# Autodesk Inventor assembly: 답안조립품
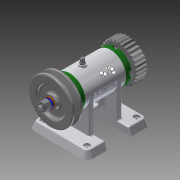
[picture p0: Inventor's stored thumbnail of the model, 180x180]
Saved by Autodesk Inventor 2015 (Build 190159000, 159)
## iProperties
Created: 2016-07
Part Number: 답안조립품
Document SubType Name: Assembly
Designer: LineLG02
Author: LineLG02
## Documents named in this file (16)
- C:\Users\LineLG02\Desktop\답안조립품.iam
- C:\Users\LineLG02\Desktop\본체.ipt
- C:\Users\LineLG02\Desktop\베어링 15 x 32 x 9.ipt
- C:\Users\LineLG02\Desktop\커버.ipt
- C:\Users\LineLG02\Desktop\볼트 M4 x 12.ipt
- C:\Users\LineLG02\Desktop\오일 실 15 25 7.ipt
- C:\Users\LineLG02\Desktop\축.ipt
- C:\Users\LineLG02\Desktop\키 3 x 3 x 12.ipt
- C:\Users\LineLG02\Desktop\V벨트풀리.ipt
- C:\Users\LineLG02\Desktop\스퍼기어.ipt
- C:\Users\LineLG02\Desktop\와셔 8x17.ipt
- C:\Users\LineLG02\Desktop\스프링와셔 8.ipt
- C:\Users\LineLG02\Desktop\너트 M 8.ipt
- C:\Users\LineLG02\Desktop\니플 M 6 x 0.75.ipt
- C:\Users\LineLG02\Desktop\와셔 6x11.5.ipt
- C:\Users\LineLG02\Desktop\볼트 M 6 x 8.ipt
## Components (11 placed, 3 different names)
1. KS B 2023 6002 - 15 x 32 x 9:1
2. KS B 2023 6002 - 15 x 32 x 9:2
3. V벨트풀리:1 — 각도:3
4. ISO 4762 M4 x 12:1 — 각도:1
5. ISO 4762 M4 x 12:3
6. ISO 4762 M4 x 12:4
7. ISO 4762 M4 x 12:5
8. ISO 4762 M4 x 12:2 — 각도:2
9. ISO 4762 M4 x 12:6
10. ISO 4762 M4 x 12:7
11. ISO 4762 M4 x 12:8
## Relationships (3: Angle 3)
- 각도:1 [Angle]: ISO 4762 M4 x 12:1
- 각도:2 [Angle]: ISO 4762 M4 x 12:2
- 각도:3 [Angle]: V벨트풀리:1
